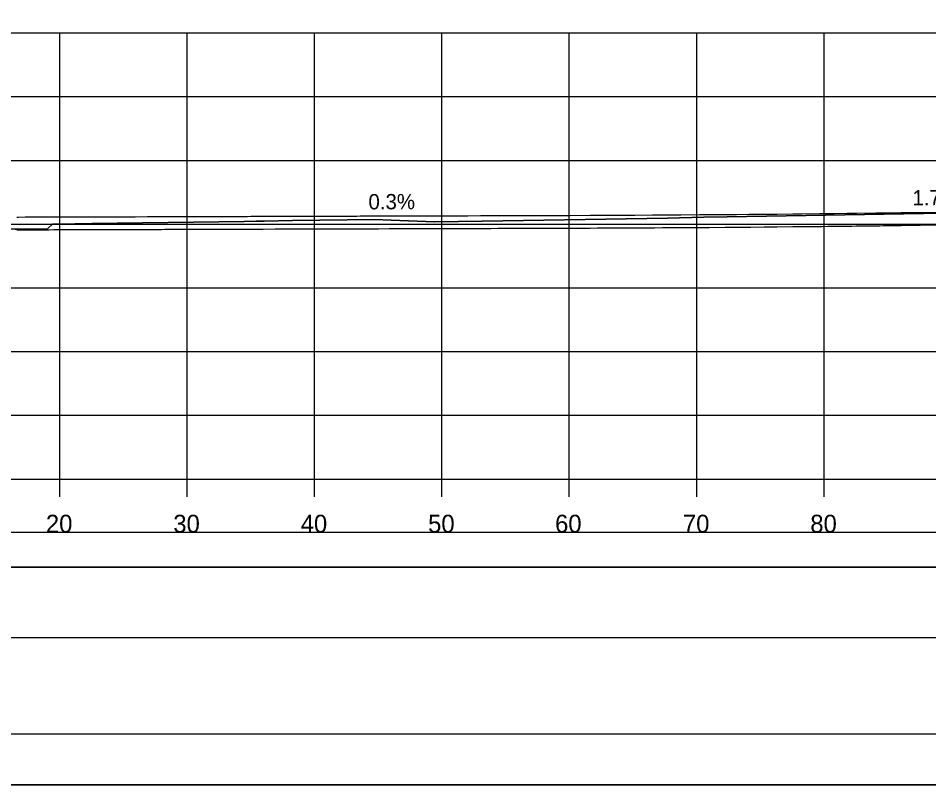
# Model space of a CAD drawing. Extents: x -37291014 to -37290680, y -936053 to -933067.
# Drawn here: x -37290826.4 to -37290754.9, y -934773.3 to -934713.1 of the extents above; entities that cross this region are included whole.
import ezdxf

# ---------------------------------------------------------------- set-up
doc = ezdxf.new("R2010")
doc.units = 0
for name, color, linetype in [('Default', 7, 'Continuous'), ('R_Alt Surface', 7, 'Continuous'), ('R_Axis', 7, 'Continuous'), ('R_Axis Annot', 7, 'Continuous'), ('R_Border', 7, 'Continuous'), ('R_Contours', 7, 'Continuous'), ('R_Exist Surface', 7, 'Continuous'), ('R_Fin Surface', 7, 'Continuous'), ('R_Grid', 7, 'Continuous'), ('R_No Plot', 7, 'Continuous'), ('R_Xsect Elev', 7, 'Continuous')]:
    doc.layers.add(name, color=color, linetype=linetype)

msp = doc.modelspace()

# ---------------------------------------------------------------- linework, layer by layer
at = {"layer": 'Default'}
for points in [[(-37290992.311, -934756.202), (-37290693.892, -934756.202), (-37290693.892, -934753.496), (-37290992.311, -934753.496)], [(-37290992.311, -934761.724), (-37290693.892, -934761.724), (-37290693.892, -934756.202), (-37290992.311, -934756.202)]]:
    msp.add_lwpolyline(points, close=True, dxfattribs=at)
at = {"layer": 'R_Alt Surface'}
msp.add_lwpolyline([(-37290826.456, -934729.739), (-37290826.349, -934729.739), (-37290825.801, -934729.737), (-37290825.785, -934729.737), (-37290825.565, -934729.736), (-37290825.533, -934729.736), (-37290825.214, -934729.735), (-37290825.079, -934729.735), (-37290824.586, -934729.733), (-37290824.519, -934729.733), (-37290824.338, -934729.733), (-37290823.919, -934729.731), (-37290823.563, -934729.73), (-37290823.436, -934729.73), (-37290823.212, -934729.729), (-37290823.101, -934729.729), (-37290822.754, -934729.728), (-37290822.466, -934729.727), (-37290822.317, -934729.727), (-37290821.912, -934729.725), (-37290821.681, -934729.725), (-37290821.163, -934729.723), (-37290821.038, -934729.723), (-37290820.857, -934729.722), (-37290820.133, -934729.72), (-37290819.995, -934729.72), (-37290819.972, -934729.72), (-37290819.196, -934729.717), (-37290819.094, -934729.717), (-37290818.747, -934729.716), (-37290818.231, -934729.714), (-37290818.155, -934729.714), (-37290818.101, -934729.714), (-37290817.486, -934729.712), (-37290817.236, -934729.711), (-37290817.178, -934729.711), (-37290816.213, -934729.708), (-37290816.191, -934729.708), (-37290816.163, -934729.708), (-37290815.163, -934729.705), (-37290815.112, -934729.705), (-37290814.862, -934729.704), (-37290814.087, -934729.702), (-37290814.023, -934729.702), (-37290813.499, -934729.7), (-37290813.101, -934729.699), (-37290812.986, -934729.699), (-37290812.898, -934729.698), (-37290812.102, -934729.696), (-37290811.861, -934729.695), (-37290811.736, -934729.695), (-37290810.712, -934729.692), (-37290810.673, -934729.692), (-37290810.538, -934729.691), (-37290809.542, -934729.688), (-37290809.305, -934729.688), (-37290809.21, -934729.687), (-37290808.35, -934729.685), (-37290808.101, -934729.684), (-37290808.037, -934729.684), (-37290807.715, -934729.683), (-37290807.138, -934729.681), (-37290806.189, -934729.678), (-37290805.907, -934729.677), (-37290804.659, -934729.674), (-37290804.63, -934729.674), (-37290803.393, -934729.67), (-37290803.101, -934729.669), (-37290803.041, -934729.669), (-37290802.112, -934729.666), (-37290801.42, -934729.664), (-37290800.817, -934729.662), (-37290799.77, -934729.659), (-37290799.508, -934729.658), (-37290798.187, -934729.654), (-37290798.101, -934729.654), (-37290798.09, -934729.654), (-37290797.236, -934729.651), (-37290796.855, -934729.65), (-37290796.444, -934729.649), (-37290796.38, -934729.649), (-37290795.514, -934729.646), (-37290794.641, -934729.644), (-37290794.163, -934729.642), (-37290793.101, -934729.639), (-37290792.874, -934729.638), (-37290792.806, -934729.638), (-37290791.442, -934729.634), (-37290791.079, -934729.633), (-37290790.074, -934729.63), (-37290789.257, -934729.627), (-37290788.701, -934729.626), (-37290788.196, -934729.624), (-37290788.101, -934729.624), (-37290787.407, -934729.622), (-37290787.326, -934729.622), (-37290787.289, -934729.622), (-37290785.985, -934729.617), (-37290785.984, -934729.617), (-37290785.372, -934729.615), (-37290785.371, -934729.615), (-37290785.169, -934729.615), (-37290784.535, -934729.612), (-37290784.535, -934729.612), (-37290783.078, -934729.607), (-37290783.072, -934729.607), (-37290783.034, -934729.607), (-37290783.026, -934729.607), (-37290783.025, -934729.607), (-37290781.467, -934729.6), (-37290781.461, -934729.6), (-37290780.893, -934729.598), (-37290780.88, -934729.598), (-37290779.837, -934729.593), (-37290779.833, -934729.593), (-37290778.742, -934729.588), (-37290778.71, -934729.587), (-37290778.142, -934729.585), (-37290777.964, -934729.584), (-37290777.963, -934729.584), (-37290777.949, -934729.584), (-37290776.561, -934729.576), (-37290776.421, -934729.576), (-37290775.782, -934729.572), (-37290775.734, -934729.572), (-37290774.632, -934729.565), (-37290774.592, -934729.565), (-37290774.356, -934729.563), (-37290772.854, -934729.554), (-37290772.792, -934729.554), (-37290772.757, -934729.553), (-37290772.198, -934729.55), (-37290772.122, -934729.549), (-37290770.88, -934729.541), (-37290770.866, -934729.54), (-37290770.813, -934729.54), (-37290769.98, -934729.534), (-37290769.001, -934729.526), (-37290768.867, -934729.525), (-37290767.813, -934729.516), (-37290767.739, -934729.515), (-37290767.573, -934729.514), (-37290766.974, -934729.508), (-37290766.78, -934729.506), (-37290765.548, -934729.495), (-37290765.474, -934729.494), (-37290764.885, -934729.488), (-37290764.812, -934729.487), (-37290763.461, -934729.473), (-37290763.252, -934729.471), (-37290762.807, -934729.466), (-37290762.735, -934729.465), (-37290762.324, -934729.461), (-37290761.302, -934729.449), (-37290760.923, -934729.444), (-37290760.59, -934729.44), (-37290760.522, -934729.439), (-37290759.041, -934729.422), (-37290758.74, -934729.418), (-37290758.449, -934729.414), (-37290758.202, -934729.41), (-37290757.065, -934729.396), (-37290756.224, -934729.385), (-37290755.563, -934729.376), (-37290753.689, -934729.351)], dxfattribs=at)
at = {"layer": 'R_Axis'}
for p, q in [((-37290993.102, -934749.296), (-37290693.102, -934749.296)), ((-37290823.102, -934750.696), (-37290823.102, -934749.296)), ((-37290813.102, -934750.696), (-37290813.102, -934749.296)), ((-37290803.102, -934750.696), (-37290803.102, -934749.296)), ((-37290793.102, -934750.696), (-37290793.102, -934749.296)), ((-37290783.102, -934750.696), (-37290783.102, -934749.296)), ((-37290773.102, -934750.696), (-37290773.102, -934749.296)), ((-37290763.102, -934750.696), (-37290763.102, -934749.296))]:
    msp.add_line(p, q, dxfattribs=at)
at = {"layer": 'R_Border'}
msp.add_line((-37290684.921, -934769.296), (-37291001.102, -934769.296), dxfattribs=at)
at = {"layer": 'R_Contours'}
for points in [[(-37290753.749, -934728.43), (-37290770.725, -934728.726), (-37290772.541, -934728.76), (-37290775.384, -934728.834), (-37290789.937, -934729.061), (-37290793.653, -934729.122), (-37290793.669, -934729.117), (-37290793.679, -934729.106), (-37290797.085, -934728.973), (-37290798.405, -934728.922), (-37290804.835, -934729.022), (-37290807.064, -934729.056), (-37290807.672, -934729.064), (-37290808.615, -934729.079), (-37290820.571, -934729.253), (-37290823.266, -934729.293), (-37290823.597, -934729.287), (-37290823.666, -934729.289), (-37290824.013, -934729.614), (-37290824.091, -934729.698), (-37290826.595, -934729.696), (-37290832.101, -934729.689)], [(-37290826.456, -934729.739), (-37290826.349, -934729.739), (-37290825.801, -934729.737), (-37290825.785, -934729.737), (-37290825.565, -934729.736), (-37290825.533, -934729.736), (-37290825.214, -934729.735), (-37290825.079, -934729.735), (-37290824.586, -934729.733), (-37290824.519, -934729.733), (-37290824.338, -934729.733), (-37290823.919, -934729.731), (-37290823.563, -934729.73), (-37290823.436, -934729.73), (-37290823.212, -934729.729), (-37290823.101, -934729.729), (-37290822.754, -934729.728), (-37290822.466, -934729.727), (-37290822.317, -934729.727), (-37290821.912, -934729.725), (-37290821.681, -934729.725), (-37290821.163, -934729.723), (-37290821.038, -934729.723), (-37290820.857, -934729.722), (-37290820.133, -934729.72), (-37290819.995, -934729.72), (-37290819.972, -934729.72), (-37290819.196, -934729.717), (-37290819.094, -934729.717), (-37290818.747, -934729.716), (-37290818.231, -934729.714), (-37290818.155, -934729.714), (-37290818.101, -934729.714), (-37290817.486, -934729.712), (-37290817.236, -934729.711), (-37290817.178, -934729.711), (-37290816.213, -934729.708), (-37290816.191, -934729.708), (-37290816.163, -934729.708), (-37290815.163, -934729.705), (-37290815.112, -934729.705), (-37290814.862, -934729.704), (-37290814.087, -934729.702), (-37290814.023, -934729.702), (-37290813.499, -934729.7), (-37290813.101, -934729.699), (-37290812.986, -934729.699), (-37290812.898, -934729.698), (-37290812.102, -934729.696), (-37290811.861, -934729.695), (-37290811.736, -934729.695), (-37290810.712, -934729.692), (-37290810.673, -934729.692), (-37290810.538, -934729.691), (-37290809.542, -934729.688), (-37290809.305, -934729.688), (-37290809.21, -934729.687), (-37290808.35, -934729.685), (-37290808.101, -934729.684), (-37290808.037, -934729.684), (-37290807.715, -934729.683), (-37290807.138, -934729.681), (-37290806.189, -934729.678), (-37290805.907, -934729.677), (-37290804.659, -934729.674), (-37290804.63, -934729.674), (-37290803.393, -934729.67), (-37290803.101, -934729.669), (-37290803.041, -934729.669), (-37290802.112, -934729.666), (-37290801.42, -934729.664), (-37290800.817, -934729.662), (-37290799.77, -934729.659), (-37290799.508, -934729.658), (-37290798.187, -934729.654), (-37290798.101, -934729.654), (-37290798.09, -934729.654), (-37290797.236, -934729.651), (-37290796.855, -934729.65), (-37290796.444, -934729.649), (-37290796.38, -934729.649), (-37290795.514, -934729.646), (-37290794.641, -934729.644), (-37290794.163, -934729.642), (-37290793.101, -934729.639), (-37290792.874, -934729.638), (-37290792.806, -934729.638), (-37290791.442, -934729.634), (-37290791.079, -934729.633), (-37290790.074, -934729.63), (-37290789.257, -934729.627), (-37290788.701, -934729.626), (-37290788.196, -934729.624), (-37290788.101, -934729.624), (-37290787.407, -934729.622), (-37290787.326, -934729.622), (-37290787.289, -934729.622), (-37290785.985, -934729.617), (-37290785.372, -934729.615), (-37290785.169, -934729.615), (-37290784.535, -934729.612), (-37290783.078, -934729.607), (-37290783.034, -934729.607), (-37290781.467, -934729.6), (-37290780.893, -934729.598), (-37290780.88, -934729.598), (-37290779.837, -934729.593), (-37290778.742, -934729.588), (-37290778.71, -934729.587), (-37290778.142, -934729.585), (-37290777.964, -934729.584), (-37290777.949, -934729.584), (-37290776.561, -934729.576), (-37290776.421, -934729.576), (-37290775.782, -934729.572), (-37290775.734, -934729.572), (-37290774.632, -934729.565), (-37290774.592, -934729.565), (-37290774.356, -934729.563), (-37290772.854, -934729.554), (-37290772.792, -934729.554), (-37290772.757, -934729.553), (-37290772.198, -934729.55), (-37290772.122, -934729.549), (-37290770.88, -934729.541), (-37290770.866, -934729.54), (-37290770.813, -934729.54), (-37290769.98, -934729.534), (-37290769.001, -934729.526), (-37290768.867, -934729.525), (-37290767.813, -934729.516), (-37290767.739, -934729.515), (-37290767.573, -934729.514), (-37290766.974, -934729.508), (-37290766.78, -934729.506), (-37290765.548, -934729.495), (-37290765.474, -934729.494), (-37290764.885, -934729.488), (-37290764.812, -934729.487), (-37290763.461, -934729.473), (-37290763.252, -934729.471), (-37290762.807, -934729.466), (-37290762.735, -934729.465), (-37290762.324, -934729.461), (-37290761.302, -934729.449), (-37290760.923, -934729.444), (-37290760.59, -934729.44), (-37290760.522, -934729.439), (-37290759.041, -934729.422), (-37290758.74, -934729.418), (-37290758.449, -934729.414), (-37290758.202, -934729.41), (-37290757.065, -934729.396), (-37290756.224, -934729.385), (-37290755.563, -934729.376), (-37290753.689, -934729.351)]]:
    msp.add_lwpolyline(points, dxfattribs=at)
at = {"layer": 'R_Exist Surface'}
msp.add_lwpolyline([(-37290826.595, -934729.696), (-37290824.091, -934729.698), (-37290824.013, -934729.614), (-37290823.666, -934729.289), (-37290823.597, -934729.287), (-37290823.266, -934729.293), (-37290820.571, -934729.253), (-37290808.615, -934729.079), (-37290807.672, -934729.064), (-37290807.064, -934729.056), (-37290804.835, -934729.022), (-37290798.405, -934728.922), (-37290797.085, -934728.973), (-37290793.679, -934729.106), (-37290793.669, -934729.117), (-37290793.665, -934729.122), (-37290793.653, -934729.122), (-37290789.937, -934729.061), (-37290775.384, -934728.834), (-37290772.541, -934728.76), (-37290770.725, -934728.726), (-37290753.749, -934728.43)], dxfattribs=at)
at = {"layer": 'R_Fin Surface'}
msp.add_lwpolyline([(-37290826.456, -934728.739), (-37290826.349, -934728.739), (-37290825.802, -934728.737), (-37290825.786, -934728.737), (-37290825.566, -934728.736), (-37290825.534, -934728.736), (-37290825.214, -934728.735), (-37290825.08, -934728.735), (-37290824.587, -934728.733), (-37290824.52, -934728.733), (-37290824.339, -934728.733), (-37290823.92, -934728.731), (-37290823.564, -934728.73), (-37290823.437, -934728.73), (-37290823.213, -934728.729), (-37290823.102, -934728.729), (-37290822.755, -934728.728), (-37290822.467, -934728.727), (-37290822.318, -934728.727), (-37290821.913, -934728.725), (-37290821.682, -934728.725), (-37290821.163, -934728.723), (-37290821.039, -934728.723), (-37290820.858, -934728.722), (-37290820.133, -934728.72), (-37290819.995, -934728.72), (-37290819.973, -934728.72), (-37290819.197, -934728.717), (-37290819.094, -934728.717), (-37290818.748, -934728.716), (-37290818.231, -934728.714), (-37290818.155, -934728.714), (-37290818.102, -934728.714), (-37290817.487, -934728.712), (-37290817.237, -934728.711), (-37290817.178, -934728.711), (-37290816.214, -934728.708), (-37290816.192, -934728.708), (-37290816.164, -934728.708), (-37290815.164, -934728.705), (-37290815.112, -934728.705), (-37290814.863, -934728.704), (-37290814.088, -934728.702), (-37290814.024, -934728.702), (-37290813.5, -934728.7), (-37290813.102, -934728.699), (-37290812.987, -934728.699), (-37290812.898, -934728.698), (-37290812.103, -934728.696), (-37290811.862, -934728.695), (-37290811.737, -934728.695), (-37290810.713, -934728.692), (-37290810.673, -934728.692), (-37290810.539, -934728.691), (-37290809.542, -934728.688), (-37290809.306, -934728.688), (-37290809.211, -934728.687), (-37290808.351, -934728.685), (-37290808.102, -934728.684), (-37290808.037, -934728.684), (-37290807.716, -934728.683), (-37290807.139, -934728.681), (-37290806.189, -934728.678), (-37290805.908, -934728.677), (-37290804.659, -934728.674), (-37290804.631, -934728.673), (-37290803.394, -934728.67), (-37290803.102, -934728.669), (-37290803.041, -934728.669), (-37290802.113, -934728.666), (-37290801.421, -934728.664), (-37290800.817, -934728.662), (-37290799.771, -934728.659), (-37290799.509, -934728.658), (-37290798.188, -934728.654), (-37290798.102, -934728.654), (-37290798.09, -934728.654), (-37290797.236, -934728.651), (-37290796.856, -934728.65), (-37290796.445, -934728.649), (-37290796.381, -934728.649), (-37290795.514, -934728.646), (-37290794.642, -934728.644), (-37290794.164, -934728.642), (-37290793.102, -934728.639), (-37290792.875, -934728.638), (-37290792.806, -934728.638), (-37290791.443, -934728.634), (-37290791.08, -934728.633), (-37290790.074, -934728.63), (-37290789.257, -934728.627), (-37290788.702, -934728.626), (-37290788.197, -934728.624), (-37290788.102, -934728.624), (-37290787.408, -934728.622), (-37290787.327, -934728.622), (-37290787.289, -934728.621), (-37290785.985, -934728.617), (-37290785.985, -934728.617), (-37290785.372, -934728.615), (-37290785.372, -934728.615), (-37290785.169, -934728.615), (-37290784.536, -934728.612), (-37290784.536, -934728.612), (-37290783.079, -934728.607), (-37290783.072, -934728.607), (-37290783.034, -934728.607), (-37290783.026, -934728.607), (-37290783.025, -934728.607), (-37290781.467, -934728.6), (-37290781.461, -934728.6), (-37290780.894, -934728.598), (-37290780.881, -934728.598), (-37290779.838, -934728.593), (-37290779.834, -934728.593), (-37290778.742, -934728.588), (-37290778.711, -934728.587), (-37290778.143, -934728.585), (-37290777.965, -934728.584), (-37290777.964, -934728.584), (-37290777.949, -934728.584), (-37290776.562, -934728.576), (-37290776.422, -934728.575), (-37290775.783, -934728.572), (-37290775.734, -934728.571), (-37290774.633, -934728.565), (-37290774.592, -934728.565), (-37290774.356, -934728.563), (-37290772.854, -934728.554), (-37290772.792, -934728.554), (-37290772.758, -934728.553), (-37290772.199, -934728.55), (-37290772.123, -934728.549), (-37290770.88, -934728.54), (-37290770.866, -934728.54), (-37290770.814, -934728.54), (-37290769.98, -934728.534), (-37290769.002, -934728.526), (-37290768.868, -934728.524), (-37290767.814, -934728.516), (-37290767.74, -934728.515), (-37290767.573, -934728.513), (-37290766.975, -934728.508), (-37290766.781, -934728.506), (-37290765.548, -934728.495), (-37290765.475, -934728.494), (-37290764.886, -934728.488), (-37290764.813, -934728.487), (-37290763.462, -934728.473), (-37290763.252, -934728.471), (-37290762.808, -934728.466), (-37290762.735, -934728.465), (-37290762.325, -934728.461), (-37290761.303, -934728.449), (-37290760.924, -934728.444), (-37290760.591, -934728.44), (-37290760.523, -934728.439), (-37290759.041, -934728.421), (-37290758.741, -934728.417), (-37290758.449, -934728.414), (-37290758.202, -934728.41), (-37290757.066, -934728.396), (-37290756.224, -934728.385), (-37290755.564, -934728.376), (-37290753.689, -934728.351)], dxfattribs=at)
at = {"layer": 'R_Grid'}
for p, q in [((-37290993.102, -934714.296), (-37290693.102, -934714.296)), ((-37290823.102, -934749.296), (-37290823.102, -934714.296)), ((-37290813.102, -934749.296), (-37290813.102, -934714.296)), ((-37290803.102, -934749.296), (-37290803.102, -934714.296)), ((-37290793.102, -934749.296), (-37290793.102, -934714.296)), ((-37290783.102, -934749.296), (-37290783.102, -934714.296)), ((-37290773.102, -934749.296), (-37290773.102, -934714.296)), ((-37290763.102, -934749.296), (-37290763.102, -934714.296)), ((-37290993.102, -934719.296), (-37290693.102, -934719.296)), ((-37290993.102, -934724.296), (-37290693.102, -934724.296)), ((-37290993.102, -934729.296), (-37290693.102, -934729.296)), ((-37290993.102, -934734.296), (-37290693.102, -934734.296)), ((-37290993.102, -934739.296), (-37290693.102, -934739.296)), ((-37290993.102, -934744.296), (-37290693.102, -934744.296)), ((-37290993.102, -934749.296), (-37290693.102, -934749.296))]:
    msp.add_line(p, q, dxfattribs=at)
at = {"layer": 'R_No Plot'}
msp.add_line((-37291013.502, -934773.274), (-37290680.169, -934773.274), dxfattribs=at)
for points in [[(-37291013.509, -934559.941), (-37290680.169, -934559.941), (-37290680.169, -934773.279), (-37291013.509, -934773.279)], [(-37290767.182, -934563.836), (-37290747.562, -934563.836), (-37290747.562, -934573.716), (-37290731.449, -934573.716), (-37290708.25, -934573.716), (-37290708.25, -934598.048), (-37290684.921, -934598.048), (-37290684.921, -934769.296), (-37291001.102, -934769.296), (-37291001.102, -934563.836)]]:
    msp.add_lwpolyline(points, close=True, dxfattribs=at)

# ---------------------------------------------------------------- texts
at = {"layer": 'R_Axis Annot'}
for s, p in [('20', (-37290824.187, -934753.496)), ('30', (-37290814.187, -934753.496)), ('40', (-37290804.187, -934753.496)), ('50', (-37290794.187, -934753.496)), ('60', (-37290784.221, -934753.496)), ('70', (-37290774.187, -934753.496)), ('80', (-37290764.187, -934753.496))]:
    msp.add_text(s, height=1.4, dxfattribs=at).set_placement(p)
at = {"layer": 'R_Xsect Elev'}
for s, rotation, p in [('1.7% - SANTEE DR.', 0.96422, (-37290756.161, -934727.837)), ('0.3%', 0.17189, (-37290798.867, -934728.14))]:
    msp.add_text(s, height=1.2, rotation=rotation, dxfattribs=at).set_placement(p)

doc.saveas('drawing.dxf')
